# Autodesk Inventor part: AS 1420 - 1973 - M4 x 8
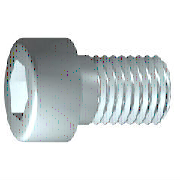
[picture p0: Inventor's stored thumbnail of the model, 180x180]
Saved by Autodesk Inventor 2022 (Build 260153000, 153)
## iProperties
Created: 2021-02
Part Number: AS 1420 - 1973 - M4 x 8
Material: Acciaio, Dolce
Description: Viti con esagono incassato metriche ISO
Document SubType Name: Modeling
Standard: AS 1420 - 1973
Designer: admin
Standards Organization: AS
Language: it-IT
Size Designation: M4 x 8
Categories: <MemberInstance><Categories><Category DisplayName="Elementi di fissaggio" InternalName="e4da775c-781d-43d5-af7c-5136215cf5a6" Mnemonic="FSTN"><Category DisplayN
Density: 7.85 g/cm^3
Appearance: Semilucidato
IsCustomPart: 0
Author: admin
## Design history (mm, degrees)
sketch "Schizzo1"
  geometry: L1 (-1, 0)-(8, 0); L2 (8, 0)-(8, 2); L3 (8, 2)-(1.75, 2); L4 (1.75, 2)-(1.32, 2); L5 (1.32, 2)-(0, 2); L6 (0, 2)-(0, 3.5); L7 (0, 3.5)-(-4, 3.5); L8 (-4, 3.5)-(-4, 1.732); L9 (-4, 1.732)-(-2, 1.732); L10 (-2, 1.732)-(-1, 0); L11 (-6.4, 0)-(10.4, 0) reference; L12 (0, -0.7)-(0, 4.2) reference; L13 (1.75, 2)-(0, 2)
  constraints: 22 end point, 6 parallel, 2 collinear, 2 perpendicular, 1 horizontal, 1 point on line
  dimensions: "d1" = 6.25 distance from line of L3.end L2 (= GEL); "d2" = 0.42952 distance of L4.end L3.end (computed from GAL); "d3" = 4 distance between parallel lines of L8 L6 (= KOH); "d4" = 2 distance of L8.end L9.end (= INTI); "d5" = 60 deg angle of L10 L1; "d6" = 4 diameter of L3 L1 (= GD); "d7" = 4 diameter of L5 L1 (= BDM); "d8" = 3.4641 diameter of L9 L1 (= 1.1547 x SW); "d9" = 7 diameter of L7 L1 (= KOD); "d26" = 8 distance between parallel lines of L12 L2 (= NLG)
revolve "Corpo" sketch "Schizzo1" stored, may be unused: angle "d10" = 90 deg
sketch "Schizzo2"
  geometry: L1 (0, -4.9)-(0, 4.9) reference; L2 (-4.9, 0)-(4.9, 0) reference; L3 (1.732, 0)-(0.866, -1.5); L4 (0.866, -1.5)-(-0.866, -1.5); L5 (-0.866, -1.5)-(-1.732, 0); L6 (-1.732, 0)-(-0.866, 1.5); L7 (-0.866, 1.5)-(0.866, 1.5); L8 (0.866, 1.5)-(1.732, 0); 2 further points
  constraints: 12 end point, 1 coincident, 1 horizontal alignment, 1 point on line, 12 other
extrude "Intaglio" join sketch "Schizzo2" stored distance "d11" = 10; taper "d12" = 0 deg
workplane "Work Plane1"
fillet "Fillet2" dims "d30" = 0.1 (= R)
body "Solid1"
fillet "Raccordo1" dims "d17" = 0.4 (= RR)
feature "Filettatura" dims "d13" = 6.25 (= GEL), "d14" = 0
chamfer "Smusso1" distance "d15" = 0.42941 (= -0.5 x SPD + 0.5 x GD); stored, may be unused: second distance "d16" = 0.42941 (= GUL), angle "d27" = 45 deg
other parameters: "GD" = 4 (= NND) [user parameter; used in 2 equation terms], "NLG" = 8 [user parameter; used in 1 equation term], "GEL" = 6.25 [user parameter; used in 2 equation terms], "KOD" = 7 [user parameter; used in 1 equation term], "KOH" = 4 (= NND) [user parameter; used in 1 equation term], "INTI" = 2 [user parameter; used in 1 equation term], "GAL" = 0.42941 (= 0.61345 x PTC) [user parameter; used in 1 equation term], "GUL" = 0.42941 (= 0.61345 x PTC) [user parameter; used in 1 equation term], "BDM" = 4 (= NND) [user parameter; used in 1 equation term], "SW" = 3 [user parameter; used in 2 equation terms], "RR" = 0.4 (= 0.1 x NND) [user parameter; used in 1 equation term], "SPD" = 3.14117 (= NND - 1.2269 x PTC) [user parameter; used in 1 equation term], "d19" = 0, "d28" = 0, "d29" = 0, "R" = 0.1 [user parameter; used in 1 equation term], "PHH" = 0.13 [user parameter], "GD1" = 3.14117 (= THREADDIA - 1.2269 x PTC) [user parameter], "THREADDIA" = 4 [user parameter; used in 1 equation term], "FAWI" = 45 deg [user parameter], "TPU" = 14.28571 (computed from PTC) [user parameter], "PTC" = 0.7 [user parameter; used in 5 equation terms], "KOH1" = 3.6 [user parameter], "NND" = 4 [user parameter; used in 5 equation terms], "TOA" = 30 deg [user parameter], "E0" = 3.465 (= 1.155 x SW) [user parameter]
